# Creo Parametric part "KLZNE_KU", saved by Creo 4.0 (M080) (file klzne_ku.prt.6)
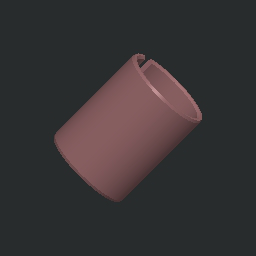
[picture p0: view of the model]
Units: millimeter Newton Second (mmNs); MM, TONNE, SECS
Materials in the file: OCEL_N

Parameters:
  NAZOV = "KLZNE_KU"
  PTC_MATERIAL_NAME = "OCEL_N"

Other parameters: HMOTNOST, HUSTOTA

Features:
  1. chamfer
  2. chamfer

Layers: ALL_AXIS, ALL_THREAD

Family table entries: GENERIC, LOZISKO_0305, KLZNE_KU, value(d_val), value(i_val), LOZISKO_0405, KLZNE_KU, LOZISKO_0505, KLZNE_KU, LOZISKO_0605, KLZNE_KU, 2/ , LOZISKO_0610, KLZNE_KU, 2/ , 2/$, LOZISKO_0810, KLZNE_KU, !/ , 2/$, 2/$, LOZISKO_0812, KLZNE_KU, !/ , 2/$, 2/(, LOZISKO_1010, KLZNE_KU, !/$, 2/(, 2/$, LOZISKO_1012, KLZNE_KU, !/$, 2/(, 2/(, LOZISKO_1015, KLZNE_KU, !/$, 2/(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

Surfaces: 4 plane, 4 cone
